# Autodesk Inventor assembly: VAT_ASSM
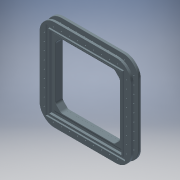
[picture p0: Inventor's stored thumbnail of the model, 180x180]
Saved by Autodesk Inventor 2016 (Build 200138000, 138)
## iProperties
Created: 2016-01
Part Number: VAT_ASSM
Document SubType Name: Assembly
Designer: John
Title: VAT_ASSM.stp
Sending System: SIEMENS PLM Software NX 7.5
Preprocessor: ST-DEVELOPER v11
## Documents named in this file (5)
- D:\3D Printer Designs\John Ledden Designs\DLP Printer\Vat-v3\VAT_ASSM.iam
- D:\3D Printer Designs\John Ledden Designs\DLP Printer\Vat-v3\Top_Clamp.ipt
- D:\3D Printer Designs\John Ledden Designs\DLP Printer\Vat-v3\FEP_FILM.ipt
- D:\3D Printer Designs\John Ledden Designs\DLP Printer\Vat-v3\3D_Riser.ipt
- D:\3D Printer Designs\John Ledden Designs\DLP Printer\Vat-v3\Base.ipt
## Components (4 placed, 4 different names)
1. Top_Clamp_1002
2. FEP_FILM_1003
3. 3D_Riser_1004
4. Base_1005
